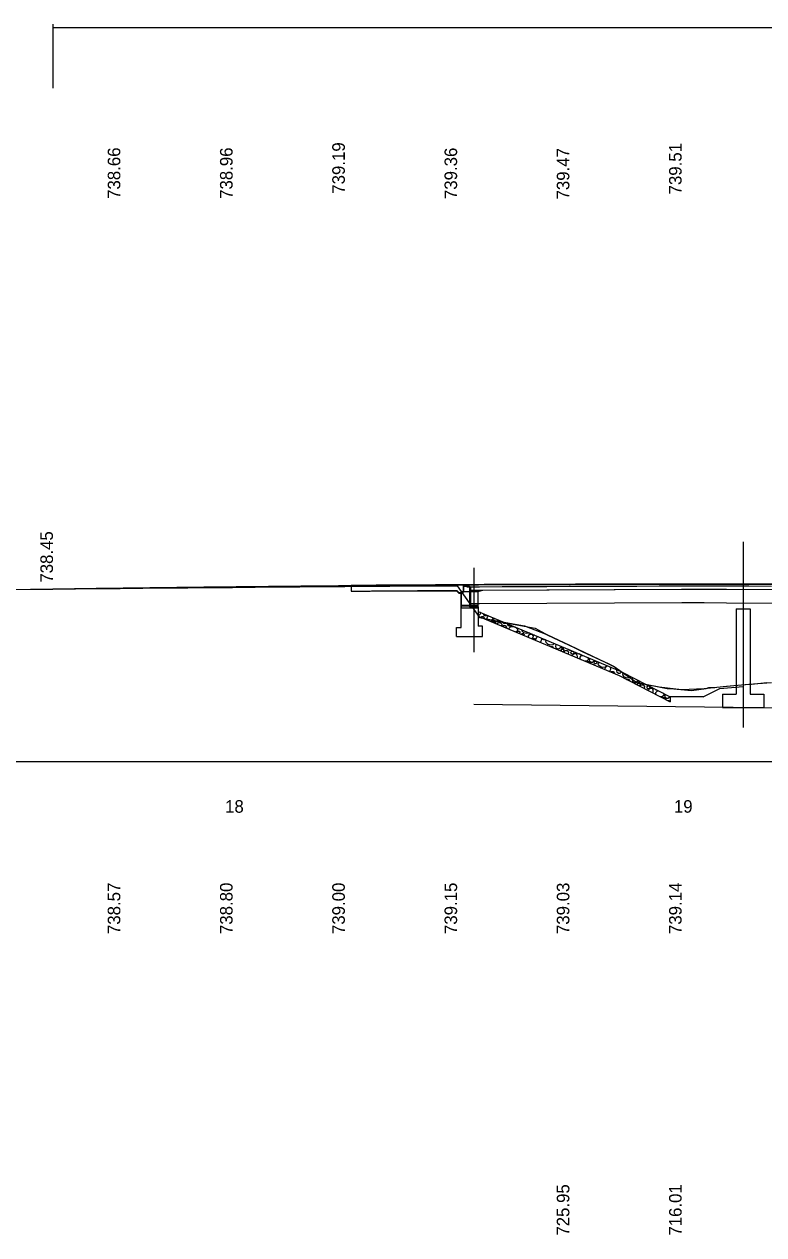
# Model space of a CAD drawing. Extents: x -434 to 1339, y -871 to 603.
# Drawn here: x 253.6 to 418.3, y -105.4 to 164.3 of the extents above; entities that cross this region are included whole.
import ezdxf

# ---------------------------------------------------------------- set-up
doc = ezdxf.new("R2010")
doc.units = 0
for name, color, linetype in [('BR_P_Brg_Pad_Object', 7, 'Continuous'), ('BR_P_Gen_Approach_Slab', 7, 'Continuous'), ('BR_P_Gen_Hatch', 7, 'Continuous'), ('BR_P_Gen_Slope_Protection', 7, 'Continuous'), ('BR_P_Slab_Object', 7, 'Continuous'), ('BR_P_Sub_Const_Joint', 7, 'Continuous'), ('BR_P_Sub_Object', 7, 'Continuous'), ('BR_X_Beam_Object', 7, 'Continuous'), ('BR_X_Gen_Approach_Slab', 7, 'Continuous'), ('BR_X_Sub_Centerline', 7, 'Continuous'), ('BR_X_Sub_Object', 7, 'Continuous'), ('Default', 7, 'Continuous'), ('GK_Cells', 7, 'Continuous'), ('PF_P_Grade_Line', 7, 'Continuous'), ('PF_P_Sta_Elev_Text', 7, 'Continuous'), ('PF_P_Text', 7, 'Continuous'), ('PF_X_Ground_Line', 7, 'Continuous'), ('SC_Scratch1', 7, 'Continuous'), ('SC_Scratch2', 7, 'Continuous'), ('XS_P_Ditch_Bottom', 7, 'Continuous'), ('XS_P_Finished_Grade', 7, 'Continuous'), ('XS_X_Ground_Line', 7, 'Continuous')]:
    doc.layers.add(name, color=color, linetype=linetype)

msp = doc.modelspace()

# ---------------------------------------------------------------- linework, layer by layer
at = {"layer": 'BR_P_Brg_Pad_Object'}
msp.add_lwpolyline([(353.21, 34.81), (354.21, 34.81), (354.21, 34.65), (353.21, 34.65)], close=True, dxfattribs=at)
at = {"layer": 'BR_P_Gen_Approach_Slab'}
for p, q in [((326.42, 39.2), (326.42, 37.95)), ((350.4, 37.66), (349.94, 38.11)), ((350.4, 37.66), (350.9, 37.66))]:
    msp.add_line(p, q, dxfattribs=at)
msp.add_open_spline([(326.42, 37.95), (334.26, 38.02), (342.1, 38.07), (349.94, 38.11)], degree=2, dxfattribs=at)
at = {"layer": 'BR_P_Gen_Hatch'}
for p, q in [((326.42, 39.2), (326.42, 37.95)), ((349.94, 38.11), (350.4, 37.66)), ((354.72, 37.87), (355.72, 38.2)), ((354.72, 34.27), (354.72, 37.87)), ((350.4, 37.66), (350.9, 37.66)), ((350.9, 37.66), (350.9, 34.27)), ((350.9, 34.27), (354.72, 34.27))]:
    msp.add_line(p, q, dxfattribs=at)
for points in [[(355.72, 38.2), (400, 38.39), (405, 38.4), (410, 38.38), (450, 38.22), (454.99, 38.18), (494.99, 37.8), (499.99, 37.75), (534.99, 37.4), (539.99, 37.35), (579.99, 36.78), (584.99, 36.71), (589.99, 36.61), (624.99, 35.92), (629.98, 35.83), (634.98, 35.69), (643.57, 35.44)], [(355.16, 33.25), (355.2, 33.2), (355.17, 32.84), (354.83, 32.55), (354.72, 32.55)], [(355.96, 32.62), (355.91, 32.94)], [(356.73, 32.59), (356.55, 32.43), (356.26, 32.42), (355.96, 32.62)], [(356.7, 31.98), (356.92, 32.49), (356.93, 32.51)], [(355.25, 32.13), (355.48, 32.32), (355.79, 32.33), (356.06, 32.04), (356.1, 31.77)], [(356.7, 31.52), (356.66, 31.67), (356.7, 32)], [(357.93, 32.08), (357.94, 31.97), (357.75, 31.4), (357.53, 31.17)], [(357.77, 31.07), (357.91, 31.23), (358.36, 31.22), (358.64, 30.87), (358.63, 30.7)], [(358.26, 31.39), (358.17, 31.87), (358.25, 31.95)], [(359.18, 31.56), (359.17, 31.48), (358.84, 31.19), (358.55, 31.19), (358.26, 31.39)], [(358.91, 30.59), (358.91, 30.6), (359.21, 30.94), (359.66, 30.93), (359.94, 30.58), (359.91, 30.22), (359.87, 30.18)], [(360.07, 30.1), (360.24, 30.28), (360.68, 30.27), (360.97, 29.92), (360.95, 29.72)], [(360.9, 30.83), (360.8, 30.74), (360.46, 30.68), (360.16, 30.95), (360.11, 31.17)], [(361.28, 30.38), (361.22, 30.7)], [(362.05, 30.35), (361.86, 30.18), (361.57, 30.18), (361.28, 30.38)], [(361.64, 29.43), (361.6, 29.71), (361.86, 30.01), (362.28, 30.1), (362.62, 30.06)], [(362.59, 30.07), (363.11, 29.85), (363.42, 29.48), (363.43, 29.16), (363.15, 28.89), (362.98, 28.87)], [(363.42, 28.69), (363.38, 28.87), (363.56, 29.07), (363.83, 29.06), (364, 28.85), (363.99, 28.64), (363.84, 28.51)], [(364.3, 28.31), (364.46, 28.5), (364.73, 28.5), (364.91, 28.29), (364.89, 28.07), (364.88, 28.07)], [(366.09, 28.64), (366, 28.56), (365.45, 28.49), (364.88, 28.68), (364.51, 29.03), (364.46, 29.33)], [(365.95, 27.62), (365.88, 28.03), (366.18, 28.37), (366.63, 28.36), (366.91, 28.01), (366.88, 27.65), (366.55, 27.36)], [(367.22, 28.17), (367.04, 28.14), (366.79, 28.35)], [(366.81, 27.25), (366.93, 27.38), (367.2, 27.38), (367.37, 27.17), (367.36, 27.02)], [(367.51, 26.96), (367.54, 27.22)], [(367.53, 27.19), (367.76, 27.71), (367.94, 27.86)], [(368.74, 27.53), (368.78, 27.19), (368.59, 26.62), (368.51, 26.54)], [(369.04, 27.28), (369.02, 27.41)], [(369.67, 27.13), (369.63, 27.09), (369.34, 27.09), (369.04, 27.28)], [(371.59, 26.32), (371.6, 26.28), (371.31, 26.01), (370.75, 25.94), (370.19, 26.13), (369.82, 26.48), (369.76, 26.82), (369.94, 27.02)], [(370.03, 25.9), (370.14, 25.89), (370.19, 25.83)], [(370.71, 25.61), (370.73, 25.64), (371.18, 25.64), (371.46, 25.29)], [(373.16, 25.66), (373.09, 25.43), (372.73, 25.07), (372.39, 25.01), (372.09, 25.28), (371.99, 25.69), (372.03, 26.03)], [(372.03, 26.01), (372.08, 26.12)], [(373.22, 24.55), (373.17, 24.82), (373.35, 25.02), (373.62, 25.01), (373.79, 24.8), (373.77, 24.59), (373.57, 24.41), (373.55, 24.41)], [(373.29, 25.28), (373.24, 25.57), (373.28, 25.61)], [(373.84, 25.38), (373.84, 25.34), (373.64, 25.16), (373.46, 25.16), (373.29, 25.28)], [(373.75, 24.33), (373.74, 24.38), (374.04, 24.71), (374.49, 24.7), (374.78, 24.35), (374.74, 23.99), (374.68, 23.94)], [(374.84, 24.93), (374.83, 24.96)], [(375.36, 24.74), (375.13, 24.73), (374.84, 24.93)], [(375.41, 24.06), (375.36, 24.35), (375.54, 24.55), (375.81, 24.55)], [(375.81, 24.54), (375.98, 24.34), (375.96, 24.12), (375.76, 23.95), (375.59, 23.95), (375.41, 24.06)], [(375.63, 23.54), (375.73, 23.77), (376.1, 24.08), (376.41, 24.09), (376.68, 23.8), (376.75, 23.25), (376.7, 23.09)], [(377.61, 23.79), (377.46, 23.79), (377.2, 23.96)], [(377.65, 22.68), (377.44, 22.88), (377.38, 23.23), (377.65, 23.53), (378.02, 23.61)], [(379.06, 23.17), (379.21, 23), (379.22, 22.68), (378.94, 22.41), (378.44, 22.35)], [(378.87, 22.17), (378.98, 22.29), (379.42, 22.29), (379.71, 21.94), (379.7, 21.82)], [(379.59, 22.28), (379.51, 22.76), (379.65, 22.93)], [(380.52, 22.56), (380.51, 22.38), (380.17, 22.09), (379.88, 22.09), (379.59, 22.28)], [(380.08, 21.66), (380.09, 21.67), (380.4, 21.67), (380.65, 21.42)], [(380.56, 21.89), (380.51, 22.18), (380.69, 22.38), (380.96, 22.37), (381.13, 22.16), (381.11, 21.95), (380.91, 21.77), (380.73, 21.77), (380.56, 21.89)], [(383.24, 21.41), (383.24, 21.29), (382.96, 21.02), (382.4, 20.95), (381.83, 21.14), (381.47, 21.49), (381.41, 21.84), (381.63, 22.09)], [(381.51, 21.06), (381.72, 21.05), (381.82, 20.92)], [(382.89, 20.47), (382.9, 20.56)], [(382.9, 20.54), (383.12, 21.05), (383.44, 21.33)], [(384.08, 21.06), (384.14, 20.53), (383.97, 20.02)], [(384.18, 19.93), (384.29, 20.05), (384.74, 20.04), (385.03, 19.69), (385.02, 19.58)], [(385.62, 19.82), (385.54, 20.3), (385.63, 20.4)], [(386.55, 20.02), (386.54, 19.92), (386.21, 19.63), (385.92, 19.63), (385.62, 19.82)], [(388.7, 18.9), (388.7, 18.85), (388.4, 18.61), (387.84, 18.58), (387.28, 18.81), (386.95, 19.19), (386.92, 19.54), (387.1, 19.72)], [(387.12, 18.59), (387.22, 18.58), (387.26, 18.51)], [(387.76, 18.26), (387.8, 18.29), (388.24, 18.25), (388.5, 17.88)], [(390.22, 18.12), (390.12, 17.9), (389.75, 17.56), (389.4, 17.53), (389.12, 17.82), (389.06, 18.24), (389.12, 18.58)], [(389.11, 18.55), (389.17, 18.66)], [(390.19, 17.01), (390.16, 17.28), (390.36, 17.46), (390.62, 17.44), (390.78, 17.22), (390.74, 17), (390.53, 16.85), (390.51, 16.85)], [(390.31, 17.73), (390.28, 18.02), (390.33, 18.07)], [(390.87, 17.79), (390.87, 17.75), (390.65, 17.59), (390.48, 17.6), (390.31, 17.73)], [(390.71, 16.75), (390.7, 16.8), (391.02, 17.11), (391.47, 17.07), (391.73, 16.69), (391.67, 16.34), (391.6, 16.29)], [(391.83, 17.27), (391.83, 17.29)], [(392.34, 17.03), (392.11, 17.05), (391.83, 17.27)], [(392.34, 16.36), (392.31, 16.65), (392.51, 16.84), (392.77, 16.81)], [(392.78, 16.81), (392.93, 16.59), (392.9, 16.38), (392.68, 16.22), (392.51, 16.23), (392.34, 16.36)], [(392.52, 15.82), (392.63, 16.04), (393.02, 16.32), (393.34, 16.31), (393.59, 16.01), (393.62, 15.44), (393.55, 15.29)], [(394.51, 15.92), (394.36, 15.93), (394.12, 16.12)], [(394.47, 14.82), (394.28, 15.03), (394.25, 15.38), (394.53, 15.66), (394.91, 15.72)], [(395.91, 15.2), (396.05, 15.01), (396.03, 14.7), (395.73, 14.45), (395.23, 14.43)], [(395.64, 14.21), (395.76, 14.33), (396.21, 14.29), (396.47, 13.91), (396.45, 13.8)], [(396.37, 14.27), (396.33, 14.76), (396.48, 14.91)], [(397.32, 14.47), (397.3, 14.3), (396.94, 14.04), (396.65, 14.05), (396.37, 14.27)], [(396.82, 13.61), (396.82, 13.62), (397.14, 13.6), (397.37, 13.33)]]:
    msp.add_lwpolyline(points, dxfattribs=at)
msp.add_spline([(673, 35.8), (672.8, 35.81), (663.2, 36.07), (653.6, 36.32), (644, 36.56), (634.4, 36.79), (624.8, 37.01), (615.2, 37.23), (605.6, 37.43), (596, 37.62), (586.4, 37.81), (576.8, 37.98), (567.2, 38.15), (557.6, 38.3), (548, 38.45), (538.4, 38.59), (528.8, 38.72), (519.2, 38.83), (509.6, 38.94), (500, 39.04), (490.4, 39.13), (480.8, 39.21), (471.2, 39.28), (461.6, 39.34), (452, 39.4), (442.4, 39.44), (432.8, 39.47), (423.2, 39.5), (413.6, 39.51), (404, 39.51), (394.4, 39.51), (384.8, 39.5), (375.2, 39.47), (365.6, 39.44), (356, 39.4), (346.4, 39.34), (336.8, 39.28), (327.2, 39.21), (326.42, 39.2)], degree=3, dxfattribs=at)
msp.add_open_spline([(326.42, 37.95), (334.26, 38.02), (342.1, 38.07), (349.94, 38.11)], degree=2, dxfattribs=at)
at = {"layer": 'BR_P_Gen_Slope_Protection'}
for p, q in [((354.72, 33.44), (386.66, 19.97)), ((354.72, 32.35), (386.08, 19.13)), ((386.08, 19.13), (397.42, 13.27)), ((386.77, 19.9), (397.42, 14.4)), ((397.42, 14.4), (397.42, 13.27))]:
    msp.add_line(p, q, dxfattribs=at)
at = {"layer": 'BR_P_Slab_Object'}
msp.add_lwpolyline([(355.72, 38.2), (400, 38.39), (405, 38.4), (410, 38.38), (450, 38.22), (454.99, 38.18), (494.99, 37.8), (499.99, 37.75), (534.99, 37.4), (539.99, 37.35), (579.99, 36.78), (584.99, 36.71), (589.99, 36.61), (624.99, 35.92), (629.98, 35.83), (634.98, 35.69), (643.57, 35.44)], dxfattribs=at)
at = {"layer": 'BR_P_Sub_Const_Joint'}
msp.add_line((351.42, 37.87), (354.72, 37.87), dxfattribs=at)
at = {"layer": 'BR_P_Sub_Object'}
for p, q in [((350.9, 34.81), (350.9, 37.87)), ((350.9, 37.87), (351.42, 37.87)), ((351.42, 37.87), (351.42, 39.37)), ((354.72, 37.87), (355.72, 38.2)), ((354.72, 34.81), (354.72, 37.87)), ((350.9, 34.81), (354.72, 34.81)), ((350.9, 34.65), (354.72, 34.65)), ((350.9, 34.27), (350.9, 34.65)), ((350.9, 34.27), (354.72, 34.27)), ((354.72, 34.27), (354.72, 34.65))]:
    msp.add_line(p, q, dxfattribs=at)
at = {"layer": 'BR_X_Beam_Object'}
msp.add_line((352.99, 38.93), (352.99, 35.18), dxfattribs=at)
for points in [[(352.99, 38.18), (355, 38.19), (400, 38.39), (405, 38.4), (410, 38.38), (450, 38.22), (454.99, 38.18), (494.99, 37.8), (499.99, 37.75), (534.99, 37.4), (539.99, 37.35), (579.99, 36.78), (584.99, 36.71), (589.99, 36.61), (624.99, 35.92), (629.98, 35.83), (634.98, 35.69), (644.98, 35.4), (646.43, 35.36)], [(352.99, 35.18), (355.02, 35.19), (400.01, 35.39), (405, 35.4), (409.98, 35.38), (449.98, 35.22), (454.97, 35.18), (494.96, 34.8), (499.96, 34.75), (534.96, 34.4), (539.96, 34.35), (579.95, 33.78), (584.94, 33.71), (589.93, 33.61), (624.93, 32.92), (629.91, 32.83), (634.89, 32.69), (644.89, 32.41), (646.43, 32.36)]]:
    msp.add_lwpolyline(points, dxfattribs=at)
at = {"layer": 'BR_X_Gen_Approach_Slab'}
for q in [(349.85, 38.06), (350.9, 37.52)]:
    msp.add_line((350.4, 37.52), q, dxfattribs=at)
msp.add_lwpolyline([(326.42, 37.93), (330.01, 37.95), (335.01, 37.99), (340.01, 38.02), (345, 38.04), (349.85, 38.06)], dxfattribs=at)
at = {"layer": 'BR_X_Sub_Centerline'}
for p, q in [((413.71, 48.91), (413.71, 7.61)), ((353.71, 43.16), (353.71, 24.39))]:
    msp.add_line(p, q, dxfattribs=at)
at = {"layer": 'BR_X_Sub_Object'}
for p, q in [((351.42, 39.06), (352.74, 39.06)), ((351.42, 39.06), (351.42, 37.73)), ((352.74, 39.06), (352.74, 34.44)), ((350.9, 29.88), (350.9, 37.73)), ((350.9, 37.73), (351.42, 37.73)), ((352.74, 34.44), (354.72, 34.44)), ((354.72, 34.44), (354.72, 30.13)), ((412.13, 33.98), (412.13, 15)), ((412.13, 33.98), (415.29, 33.98)), ((415.29, 33.98), (415.29, 15)), ((349.9, 27.88), (349.9, 29.88)), ((349.9, 29.88), (350.9, 29.88)), ((355.65, 30.13), (354.72, 30.13)), ((355.65, 27.88), (355.65, 30.13)), ((349.9, 27.88), (355.65, 27.88)), ((409.13, 15), (412.13, 15)), ((409.13, 15), (409.13, 12)), ((415.29, 15), (418.29, 15)), ((418.29, 15), (418.29, 12)), ((409.13, 12), (418.29, 12))]:
    msp.add_line(p, q, dxfattribs=at)
at = {"layer": 'Default'}
msp.add_line((0, 0), (1050.49, 0), dxfattribs=at)
at = {"layer": 'GK_Cells'}
msp.add_line((0, 0), (1000, 0), dxfattribs=at)
at = {"layer": 'PF_P_Grade_Line'}
msp.add_spline([(260, 38.45), (269.6, 38.59), (279.2, 38.71), (288.8, 38.83), (298.4, 38.94), (308, 39.04), (317.6, 39.13), (327.2, 39.21), (336.8, 39.28), (346.4, 39.34), (356, 39.4), (365.6, 39.44), (375.2, 39.47), (384.8, 39.5), (394.4, 39.51), (404, 39.51), (413.6, 39.51), (423.2, 39.5), (432.8, 39.47), (442.4, 39.44), (452, 39.4), (461.6, 39.34), (471.2, 39.28), (480.8, 39.21), (490.4, 39.13), (500, 39.04), (509.6, 38.94), (519.2, 38.83), (528.8, 38.72), (538.4, 38.59), (548, 38.45), (557.6, 38.3), (567.2, 38.15), (576.8, 37.98), (586.4, 37.81), (596, 37.62), (605.6, 37.43), (615.2, 37.23), (624.8, 37.01), (634.4, 36.79), (644, 36.56), (653.6, 36.32), (663.2, 36.07), (672.8, 35.81), (682.4, 35.54), (692, 35.26), (701.6, 34.97), (711.2, 34.67), (720.8, 34.36), (730.4, 34.05), (740, 33.72)], degree=3, dxfattribs=at)
at = {"layer": 'PF_P_Text'}
for p, q in [((260, 164.25), (260, 150)), ((260, 163.55), (740, 163.55))]:
    msp.add_line(p, q, dxfattribs=at)
at = {"layer": 'PF_X_Ground_Line'}
msp.add_lwpolyline([(352.19, 38.93), (355, 38.94), (360, 38.96), (365, 38.99), (370, 39.01), (375, 39.03), (380, 39.05), (385, 39.07), (390, 39.09), (395, 39.12), (400, 39.14), (405, 39.15), (410, 39.13), (415, 39.11), (420, 39.09)], dxfattribs=at)
at = {"layer": 'SC_Scratch1'}
msp.add_line((499.7, 11), (353.71, 12.7), dxfattribs=at)
at = {"layer": 'SC_Scratch2'}
msp.add_lwpolyline([(250, 38.32), (255, 38.37), (260, 38.42), (265, 38.47), (270, 38.52), (275, 38.57), (280, 38.62), (285, 38.67), (290, 38.72), (295, 38.76), (300, 38.8), (305, 38.84), (310, 38.88), (315, 38.92), (320, 38.96), (325, 39), (330, 39.04), (335, 39.08), (340, 39.11), (345, 39.13), (350, 39.15), (355, 32.09), (360, 31.13), (365, 30.24), (370, 28.31), (375, 25.95), (380, 23.58), (385, 21.14), (390, 17.61), (395, 16.64), (400, 16.01), (405, 16.27), (410, 16.79), (415, 17.22), (420, 17.63)], dxfattribs=at)
at = {"layer": 'XS_P_Ditch_Bottom'}
msp.add_line((404.77, 14.4), (397.42, 14.4), dxfattribs=at)
at = {"layer": 'XS_P_Finished_Grade'}
for p, q in [((404.77, 14.4), (408.53, 16.28)), ((408.53, 16.28), (413.72, 16.71))]:
    msp.add_line(p, q, dxfattribs=at)
at = {"layer": 'XS_X_Ground_Line'}
for p, q in [((360.07, 31.03), (367.35, 29.73)), ((367.35, 29.73), (370.2, 28.15)), ((370.2, 28.15), (376.08, 25.41)), ((376.08, 25.41), (377.88, 24.52)), ((377.88, 24.52), (383.79, 21.8)), ((383.79, 21.8), (385.31, 20.95)), ((385.31, 20.95), (390.01, 17.57)), ((390.01, 17.57), (396.77, 16.3)), ((396.77, 16.3), (397.45, 16.24)), ((397.45, 16.24), (402.21, 15.79)), ((402.21, 15.79), (405.45, 16.3)), ((405.45, 16.3), (406.04, 16.52)), ((406.04, 16.52), (407.38, 16.49)), ((407.38, 16.49), (407.85, 16.54)), ((407.85, 16.54), (411.6, 16.93)), ((411.6, 16.93), (414.24, 17.14)), ((414.24, 17.14), (415.17, 17.21)), ((415.17, 17.21), (415.53, 17.24)), ((415.53, 17.24), (416.22, 17.29)), ((416.22, 17.29), (419, 17.57))]:
    msp.add_line(p, q, dxfattribs=at)
msp.add_lwpolyline([(250, 38.32), (255, 38.37), (260, 38.42), (265, 38.47), (270, 38.52), (275, 38.57), (280, 38.62), (285, 38.67), (290, 38.72), (295, 38.76), (300, 38.8), (305, 38.84), (310, 38.88), (315, 38.92), (320, 38.96), (325, 39), (330, 39.04), (335, 39.08), (340, 39.11), (345, 39.13), (350, 39.15), (355, 32.09), (360.07, 31.03)], dxfattribs=at)

# ---------------------------------------------------------------- texts
at = {"layer": 'Default'}
for s, p in [('738.57', (275, -38.43)), ('738.80', (300, -38.43)), ('739.00', (325, -38.43)), ('739.15', (350, -38.43)), ('739.03', (375, -38.43)), ('739.14', (400, -38.43)), ('725.95', (375, -105.62)), ('716.01', (400, -105.62))]:
    msp.add_text(s, height=2.8, rotation=90, dxfattribs=at).set_placement(p)
at = {"layer": 'PF_P_Sta_Elev_Text'}
for s, p in [('18', (298.33, -11.4)), ('19', (398.28, -11.4)), ('19', (398.28, -11.4))]:
    msp.add_text(s, height=2.8, dxfattribs=at).set_placement(p)
at = {"layer": 'PF_P_Text'}
for s, p in [('739.19', (325, 126.49)), ('739.51', (400, 126.34)), ('738.66', (275, 125.34)), ('738.96', (300, 125.34)), ('739.36', (350, 125.3)), ('739.47', (375, 125.21)), ('738.45', (260, 39.85))]:
    msp.add_text(s, height=2.8, rotation=90, dxfattribs=at).set_placement(p)

doc.saveas('drawing.dxf')
